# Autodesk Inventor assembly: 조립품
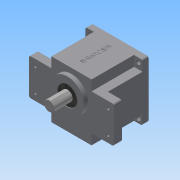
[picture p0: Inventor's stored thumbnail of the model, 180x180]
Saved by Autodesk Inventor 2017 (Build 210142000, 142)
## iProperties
Part Number: 조립품
Material: 일반
Document SubType Name: Assembly
Designer: user
Author: user
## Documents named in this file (10)
- C:\Users\user\Desktop\700116V1010\조립품.iam
- C:\Users\user\Desktop\700116V1010\본체.ipt
- C:\Users\user\Desktop\700116V1010\커버.ipt
- C:\Users\user\Desktop\700116V1010\메인 축.ipt
- C:\Users\user\Desktop\700116V1010\베어링 6003.ipt
- C:\Users\user\Desktop\700116V1010\서브 축.ipt
- C:\Users\user\Desktop\700116V1010\오일 실 8 22 7.ipt
- C:\Users\user\Desktop\700116V1010\오일 실 17 32 8.ipt
- C:\Users\user\Desktop\700116V1010\볼트 M4.ipt
- C:\Users\user\Desktop\700116V1010\베어링 608.ipt
